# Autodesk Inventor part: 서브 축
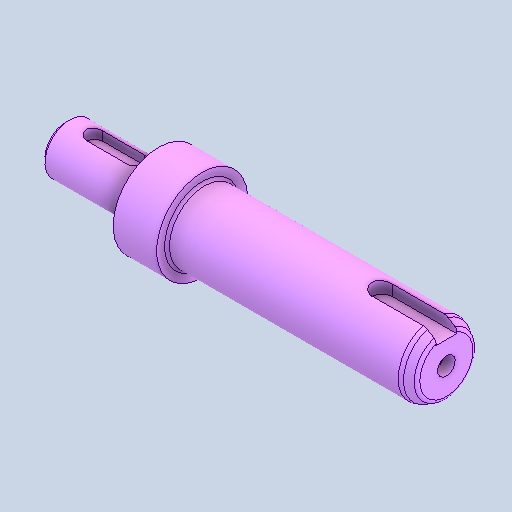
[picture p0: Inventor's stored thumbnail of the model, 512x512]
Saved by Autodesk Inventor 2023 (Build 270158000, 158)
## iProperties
Created: 2025-04
Part Number: 서브 축
Material: 강철, 탄소
Document SubType Name: Modeling
Designer: user
Density: 7.85 g/cm^3
Appearance: 기본값
Author: jhkim
Sending System: Autodesk Inventor 2026
Preprocessor: ST-DEVELOPER v20.1
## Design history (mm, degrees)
feature "솔리드1"
node "솔리드2"
